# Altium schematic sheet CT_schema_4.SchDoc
size 297 x 271 mm
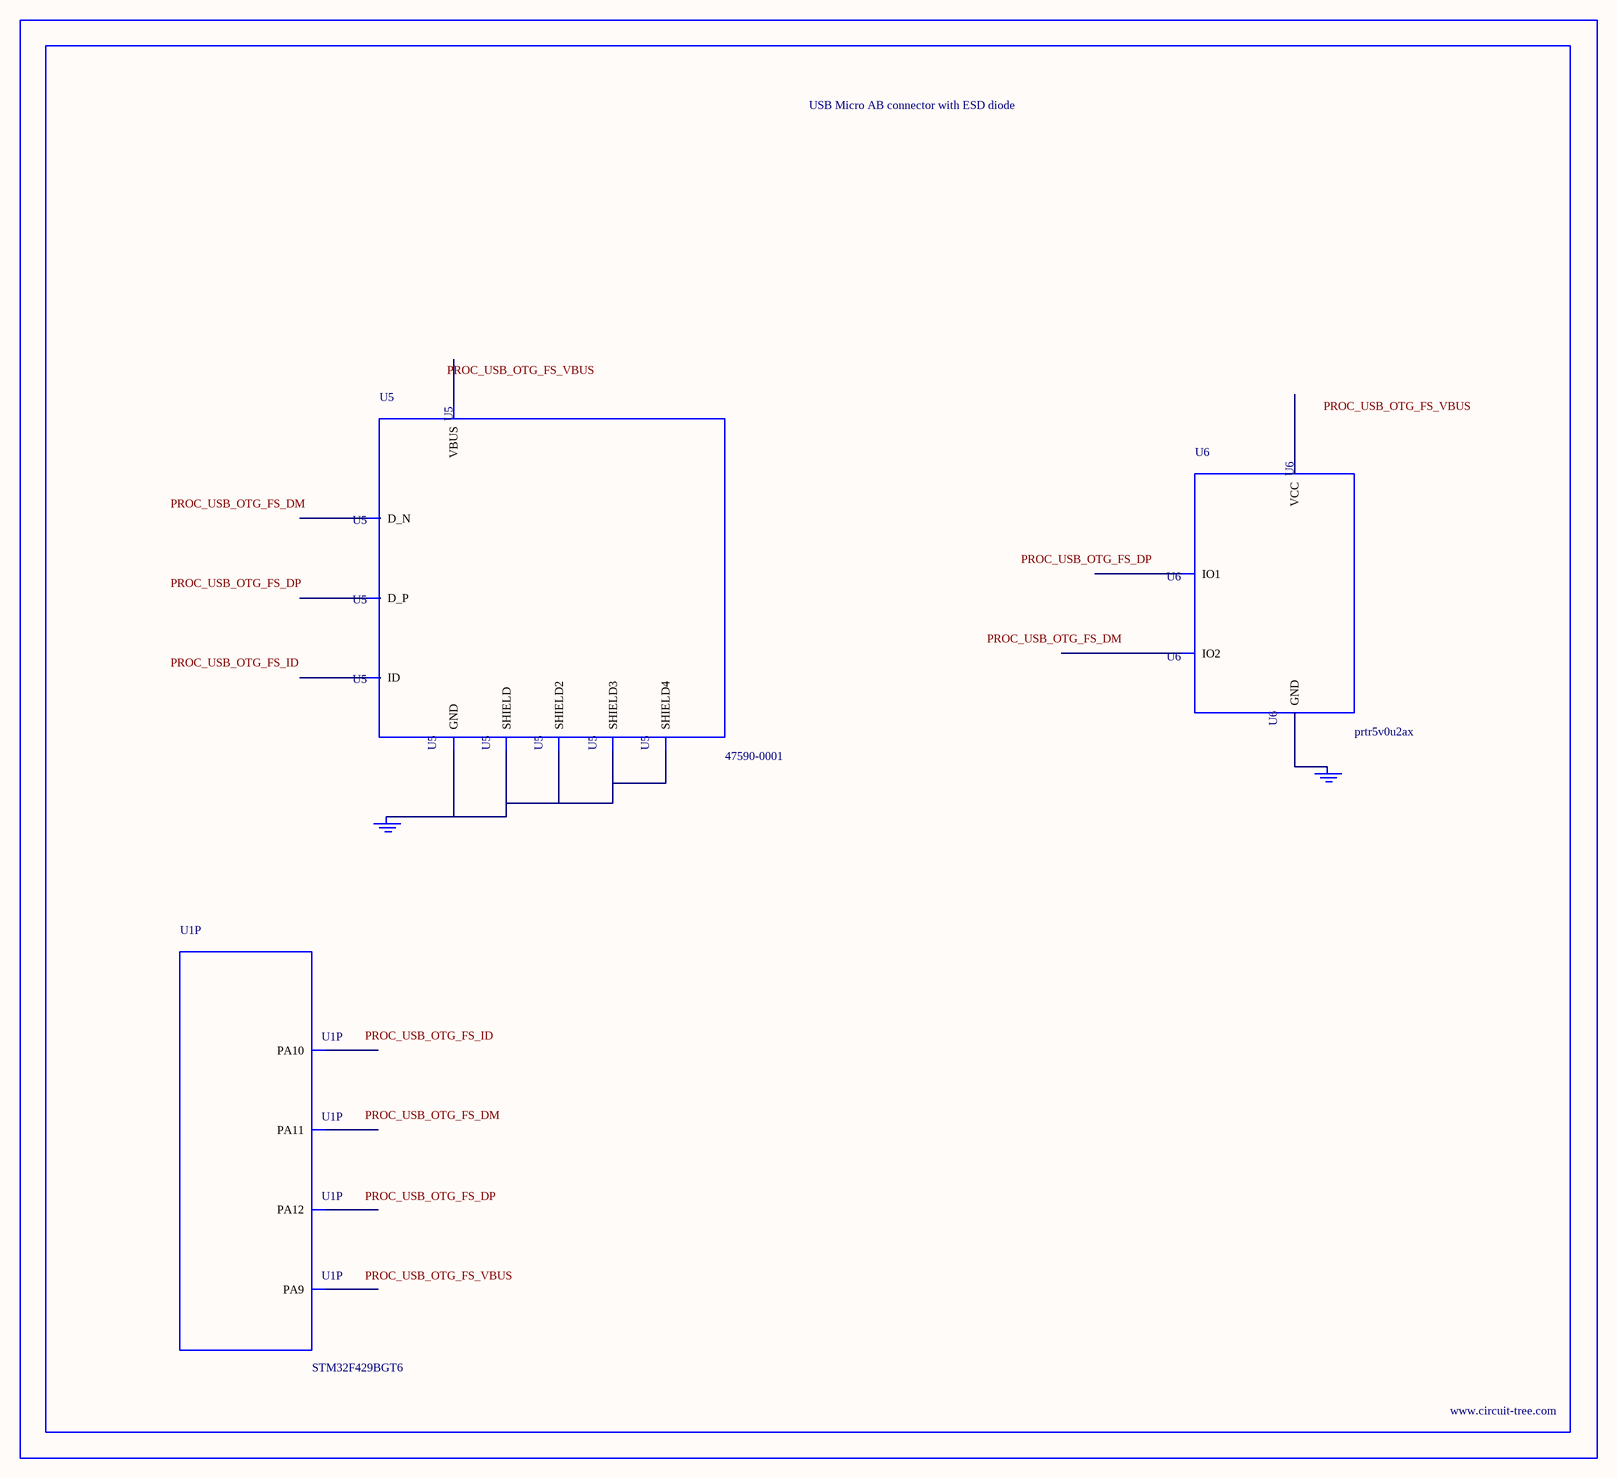
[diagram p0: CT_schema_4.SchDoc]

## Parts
BORDER3  (no value)
GND_INSTANCE_3_0  (no value)
GND_INSTANCE_3_1  (no value)
U1  STM32F429BGT6  [LQFP208]  (part P of 17)
U5  47590-0001  [MICRO_USB_AB]
U6  prtr5v0u2ax  [SOT143B]

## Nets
NetGND_INSTANCE_3_0_0: GND_INSTANCE_3_0.0(GND) U5.5(GND) U5.6(SHIELD) U5.7(SHIELD2) U5.8(SHIELD3) U5.9(SHIELD4)
NetGND_INSTANCE_3_1_0: GND_INSTANCE_3_1.0(GND) U6.1(GND)

Not connected (* = marked no-connect by the designer): U1 143(PA9) 144(PA10) 145(PA11) 146(PA12); U5 1(VBUS) 2(D_N) 3(D_P) 4(ID); U6 2(IO1) 3(IO2) 4(VCC)

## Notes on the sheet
- Labels drawn without touching a wire or pin: PROC_USB_OTG_FS_DM, PROC_USB_OTG_FS_DP, PROC_USB_OTG_FS_ID, PROC_USB_OTG_FS_VBUS

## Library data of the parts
BORDER3 = BORDER_PAGE3
GND_INSTANCE_3_0 GND_INSTANCE_3_1 = GND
